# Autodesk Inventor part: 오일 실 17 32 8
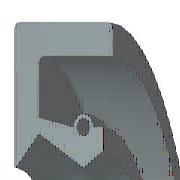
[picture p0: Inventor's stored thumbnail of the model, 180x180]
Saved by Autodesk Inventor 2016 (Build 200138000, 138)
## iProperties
IsCustomPart: 0
Created: 2018-09
Part Number: 오일 실 17 32 8
Material: 고무
Description: 오일-실
Document SubType Name: Modeling
Standard: KS B 2804
Standards Organization: KS
Language: ko-KR
Size Designation: D - 17 32 8
Categories: <MemberInstance><Categories><Category DisplayName="샤프트 부품" InternalName="7f7aeb1f-a693-4053-b835-cee3144e0d98" Mnemonic="SHFT"><Category DisplayName="실링" Intern
Density: 0.93 g/cm^3
Appearance: 고무 - 검은색 - 버전 1.1
Mass: 2.28027 g
Surface Area: 32.1224 cm^2
Volume: 2.45191 cm^3
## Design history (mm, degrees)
revolve "본체" stored, may be unused: angle "d17" = 90 deg
revolve "스프링1" stored, may be unused: angle "d18" = 90 deg
body "Solid1"
sketch "스케치1"
  geometry: L1 (0, 16)-(8, 16); L2 (8, 14.25)-(1.75, 14.25); L3 (1.75, 10.25)-(4.9, 8.5); L4 (4.9, 8.5)-(0, 8.5); L5 (0, 0)-(9.586, 0) reference; L6 (4.9, 8.5)-(6.3, 9.375); L7 (0, 18)-(0, -3) reference; L8 (-1.941, 0)-(11.507, 0) reference; L9 (4.2, 10.6)-(1.75, 11.21); L10 (1.75, 11.21)-(1.75, 14.25); L11 (0, 16)-(0, 8.588); L12 (4.9, 8.5)-(0, 8.5); L13 (1.75, 10.25)-(0.152, 8.528); L14 (8, 16)-(8, 14.25); L15 (5.6, 10.6)-(6.3, 10.6); L16 (6.3, 10.6)-(6.3, 9.375); C1 r 0.455 at (4.9, 10.6); A1 r 0.7 centre (4.9, 10.6) between (5.6, 10.6) and (4.2, 10.6); A2 r 0.088 centre (0.088, 8.588) between (0, 8.588) and (0.152, 8.528); 1 further point
  constraints: 28 end point, 5 horizontal alignment, 5 point on line, 4 point on circle, 4 vertical alignment, 3 centre point, 3 tangent, 2 collinear, 2 horizontal, 2 perpendicular, 1 coincident, 1 parallel
  dimensions: "d0" = 32 diameter of L1 L5 (= SD2); "d1" = 1.75 distance of L1.end L2.start (= SD); "d2" = 0.91 diameter of C1 (= SPDI); "d3" = 1.4 diameter of A1 (= SPDA); "d4" = 17 diameter of L3.end L5 (= NND); "d5" = 20.5 diameter of L3.start L5 (= TKDM); "d7" = 22.42 diameter of L9.end L5 (= TKDM + 0.24 x SWDT); "d8" = 1.75 distance between parallel lines of L11 L10 (= SD); "d9" = 4.9 distance from line of L11 C1.centre (= SPDST); "d10" = 21.2 diameter of C1.centre L5 (= HLDM); "d11" = 0.0875 radius of A2 (= 0.25 x LAB); "d12" = 6.3 distance between parallel lines of L11 L16 (= SDI); "d13" = 18.75 diameter of L6.end L5 (= ABDM); "d14" = 8 distance from line of L11 L1.end (= SWDT)
fillet "모깎기1" dims "d6" = 0.3 (= RR)
other parameters: "SD2" = 32 [user parameter; used in 1 equation term], "SWDT" = 8 [user parameter; used in 2 equation terms], "RR" = 0.3 [user parameter; used in 1 equation term], "SD" = 1.75 [user parameter; used in 2 equation terms], "NND" = 17 [user parameter; used in 1 equation term], "SPDA" = 1.4 [user parameter; used in 1 equation term], "SPDI" = 0.91 [user parameter; used in 1 equation term], "TKDM" = 20.5 [user parameter; used in 2 equation terms], "HLDM" = 21.2 [user parameter; used in 1 equation term], "ABDM" = 18.75 [user parameter; used in 1 equation term], "SDI" = 6.3 [user parameter; used in 1 equation term], "SPDST" = 4.9 [user parameter; used in 1 equation term], "LAB" = 0.35 [user parameter; used in 1 equation term], "d15" = 0, "d16" = 0, "d19" = 0
